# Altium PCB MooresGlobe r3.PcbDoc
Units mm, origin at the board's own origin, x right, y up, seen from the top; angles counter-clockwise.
Board outline 12 x 11 mm, 2 copper layers (Top Layer, Bottom Layer), stack 0.801 mm thick; 11 components, 6 nets, 24 pads, 3 vias.
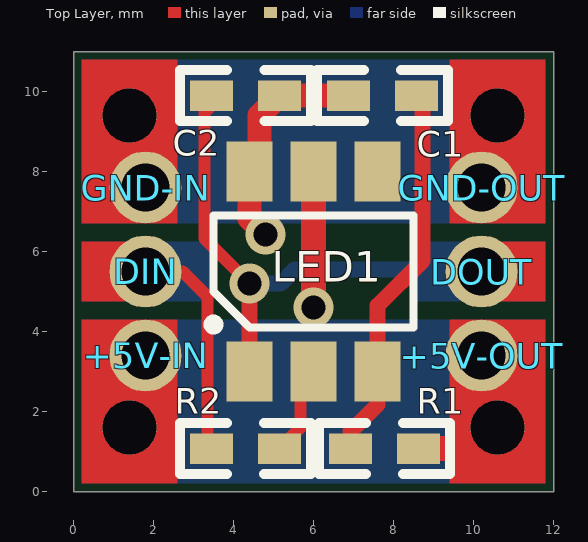
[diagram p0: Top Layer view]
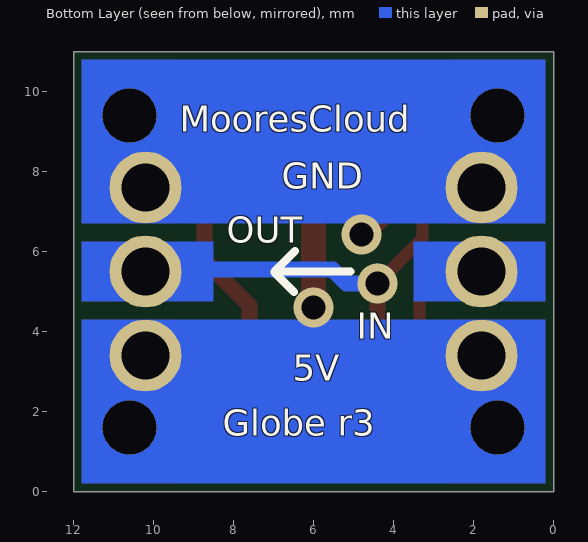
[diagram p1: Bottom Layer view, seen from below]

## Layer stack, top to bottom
Top Layer: signal copper 0.0356
Dielectric: core 0.73, FR-4, Dk 4.8
Bottom Layer: signal copper 0.0356

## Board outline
0,0 12,0 12,11 0,11

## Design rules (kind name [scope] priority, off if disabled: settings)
Clearance [All] p1: gap=0.254
HoleSize [All] p1: absolutevalues=TRUE maxlimit=3 minlimit=0.3 maxpercent=80.000 minpercent=20.000
MinimumSolderMaskSliver [All] p1: minsoldermaskwidth=0.152
PlaneClearance [All] p1: clearance=0.254
PolygonConnect [All] p1: connectstyle=Direct reliefconductorwidth=1.5 reliefentries=4 polygonreliefangle="90 Angle" airgapwidth=0.254
RoutingVias [All] p1: holewidth=0.4 width=0.6 viastyle="Through Hole" minholewidth=0.3 minwidth=0.6 maxholewidth=1 maxwidth=1.27
SilkToSilkClearance [All] p1 off: silktosilkclearance=0
SilkToSolderMaskClearance [IsPad] p1: minsilkscreentomaskgap=0.102 clearancetoexposedcopper=TRUE
SolderMaskExpansion [All] p1: expansion=0.102
Width [All] p1: maxlimit=1.27 minlimit=0.254 preferedwidth=0.254 minimp=50.000000 maximp=50.000000 favimp=50.000000
23 further rules are at their usual default settings.

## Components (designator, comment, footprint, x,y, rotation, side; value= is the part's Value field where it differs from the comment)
+5V-IN "+5V" "Solder Pad"#1 -2.3,1.7 r90 top
+5V-OUT "+5V" "Solder Pad"#2 14.027,2.326 r90 top
C1 "100n" ARA_0603 8.575,9.9 r180 top
C2 "470p" ARA_0603 3.45,9.9 r0 top
DIN "DIN" "Solder Pad"#3 -1.95,5.525 r90 top
DOUT "DOUT" "Solder Pad"#4 10.2,5.475 r90 top
GND-IN "GND" "Solder Pad"#5 -1.85,9.2 r90 top
GND-OUT "GND" "Solder Pad"#6 10.2,8.925 r90 top
LED1 "WS2812" PLCC6-IPC 6,5.5 r90 top locked
R1 "100R" ARA_0603 8.625,1.075 r180 top
R2 "0R" ARA_0603 5.15,1.075 r180 top

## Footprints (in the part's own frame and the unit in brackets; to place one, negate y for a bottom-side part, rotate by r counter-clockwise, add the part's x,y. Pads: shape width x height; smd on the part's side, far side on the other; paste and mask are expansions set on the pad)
ARA_0603 [mil]
  rect 42x30 smd: 1(0,0) 2(66.91,0)
  silkscreen extent -31,-25 98,25, body extent 0,-16 67,16, height 20
PLCC6-IPC [mm] "Leaded Chip Carrier, 12-Leads, Body 9.90x5.40mm, Pitch 1.600mm, IPC Medium Density"
  rect 1.5x1.15 smd: 1(-2.5,1.6) 2(-2.5,0) 3(-2.5,-1.6) 4(2.5,-1.6) 5(2.5,0) 6(2.5,1.6)
  silkscreen extent -1.45,-2.5 1.4,2.62, body extent -2.5,-2.5 2.5,2.5, height 1.61
"Solder Pad"#1 [mm]
  round 1.8 hole 1.2: 1(1.7,-4.1)
"Solder Pad"#2 [mm]
  round 1.8 hole 1.2: 1(1.074,3.827)
"Solder Pad"#3 [mm]
  round 1.8 hole 1.2: 1(-0.025,-3.75)
"Solder Pad"#4 [mm]
  round 1.8 hole 1.2: 1(0.025,0)
"Solder Pad"#5 [mm]
  round 1.8 hole 1.2: 1(-1.6,-3.65)
"Solder Pad"#6 [mm]
  round 1.8 hole 1.2: 1(-1.325,0)

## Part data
+5V-IN +5V-OUT DIN DOUT GND-IN GND-OUT: library part "Solder Pad", "Solder pad"
C1: library part CAP, "Capacitor Ceramic 100n 50V Y5V 0603"
C2: library part CAP, "Capacitor Ceramic 470p 50V NPO 0603"
LED1: "WorldSemi WS2812 Smart RGB LED"
R1 R2: library part "Res Semi", "Resistor 100R 0.1W 5% 0603"

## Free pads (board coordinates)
  round 1.35 hole 1.35 unplated mask+0: 0(1.4,1.6) 0(1.4,9.4) 0(10.6,1.6) 0(10.6,9.4)

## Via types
v1: diameter 1, hole 0.6, Top Layer to Bottom Layer, tented both sides, 3 vias

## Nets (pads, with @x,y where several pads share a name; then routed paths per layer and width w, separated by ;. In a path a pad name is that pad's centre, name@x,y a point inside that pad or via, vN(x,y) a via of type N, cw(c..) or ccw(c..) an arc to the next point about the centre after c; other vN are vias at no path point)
5V: +5V-IN.1 +5V-OUT.1 LED1.5 pad.0@1.4,1.6 pad.0@10.6,1.6 R1.1 | length 10.2
  Top Layer w0.635: v1(6,4.6) LED1.5 ; R1.1 9.7,1.075 ; +5V-OUT.1@9.85,3.05 +5V-OUT.1
  Bottom Layer w0.635: +5V-IN.1 5.725,3.4 6,3.675 v1(6,4.6)
DIN: DIN.1 R2.2 | length 5.8
  Top Layer w0.3: DIN.1 2.725,5.5 3.35,4.875 3.35,1.175 3.375,1.15 R2.2@3.6,1.15
DOUT: C2.1 DOUT.1 LED1.1 | length 13.7
  Top Layer w0.3: C2.1 3.45,9.65 3.275,9.475 3.275,6.325 v1(4.4,5.2)
  Top Layer w0.4: LED1.1 v1(4.4,5.2)
  Bottom Layer w0.4: v1@4.4,5.5 v1(4.4,5.2) 5.175,5.2 5.529,5.554 10.146,5.554 DOUT.1
GND: C1.2 C2.2 GND-IN.1 GND-OUT.1 LED1.6 pad.0@1.4,9.4 pad.0@10.6,9.4 | length 5.7
  Top Layer w0.6: v1(4.8,6.425) 4.4,6.825 LED1.6 4.65,8.25 4.65,9.4 C2.2 6,9.9 ; 6.025,9.9 C1.2
NetC1_1: C1.1 LED1.3 R1.2 | length 9.6
  Top Layer w0.4: R1.2 6.925,1.5 7.6,2.175 LED1.3 7.6,4.65 8.725,5.775 8.725,9.75 C1.1
NetLED1_2: LED1.2 R2.1 | length 1.8
  Top Layer w0.3: R2.1 5.675,1.6 LED1.2@5.675,2.675
pads on no net: LED1.4

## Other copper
Top Layer:
  rectangle net GND: 9.4,6.7 11.8,10.8
  rectangle net 5V: 9.4,0.2 11.8,4.3
  rectangle net 5V: 0.2,0.2 2.6,4.3
  rectangle net GND: 0.2,6.7 2.6,10.8
  rectangle net 5V: 9.75,3 11.8,4
  rectangle net GND: 9.75,7 11.8,8
  rectangle net GND: 0.2,7 2.25,8
  rectangle net 5V: 0.2,3 2.25,4
  rectangle net DIN: 0.2,4.75 2.25,6.25
  rectangle net DOUT: 9.75,4.75 11.8,6.25
Bottom Layer:
  rectangle net 5V: 0.2,0.2 11.8,4.3
  rectangle net GND: 0.2,6.7 11.8,10.8
  rectangle net 5V: 8.5,2.6 11.8,4.1
  rectangle net GND: 8.5,6.9 11.8,8.4
  rectangle net GND: 0.2,6.9 3.5,8.4
  rectangle net 5V: 0.2,2.6 3.5,4.1
  rectangle net DIN: 0.2,4.75 3.5,6.25
  rectangle net DOUT: 8.5,4.75 11.8,6.25

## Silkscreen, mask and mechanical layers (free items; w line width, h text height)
Bottom Overlay:
  lines w0.203: 5.075,5.5 6.975,5.5 6.463,6.013 ; 6.488,4.988 6.975,5.475
  text "MooresCloud" at 9.35,9 h0.65
  text "GND" at 6.8,7.575 h0.65
  text "OUT" at 8.175,6.225 h0.65
  text "IN" at 4.925,3.825 h0.65
  text "5V" at 6.525,2.775 h0.65
  text "Globe r3" at 8.275,1.4 h0.65
Mechanical 1:
  the board outline again, w0.6
Mechanical 2:
  text "Top Layer Component Keep Out Areas" at 21,4 h1
Mechanical 3:
  rectangle: 5.25,0 6.75,1.4
  rectangle: 5.25,9.6 6.75,11
  text "Bottom Layer Component Keep Out Areas" at 21,2 h1
Drill Drawing:
  lines w0.1: 21,-3.25 79.25,-3.25 ; 21,-1.25 79.25,-1.25 ; 21,7.5 79.25,7.5 ; 21,9.5 79.25,9.5 ; 21,11.5 79.25,11.5 ; 21,13.5 79.25,13.5 ; 21,15.5 79.25,15.5 ; 21,17.5 79.25,17.5 ; 21,19.5 79.25,19.5 ; 21,21.5 79.25,21.5 ; 33.5,-5.25 33.5,1 ; 33.5,5.5 33.5,23.5 ; 0,0 0,11 12,11 12,0 0,0 ; 21,-5.25 21,1 79.25,1 79.25,-5.25 21,-5.25 ; 21,5.5 79.25,5.5 79.25,23.5 21,23.5 21,5.5
  text ".legend" at 22.25,28.75 h1
  text "BOARD SIZE:" at 21.5,22 h1
  text "12.00mm x 11.00mm" at 34.5,22 h1
  text "LAYERS:" at 21.5,20 h1
  text "2" at 34.5,20 h1
  text "MATERIAL:" at 21.5,18 h1
  text "FR4 0.8mm" at 34.5,18 h1
  text "COPPER:" at 21.5,16 h1
  text "35um (after plating)" at 34.5,16 h1
  text "PTH PLATING:" at 21.5,14 h1
  text "20um (minimum)" at 34.5,14 h1
  text "FINISH:" at 21.5,12 h1
  text "ROHS HAL" at 34.5,12 h1
  text "OVERLAY:" at 21.5,10 h1
  text "Black, 2 sides" at 34.5,10 h1
  text "SOLDER MASK:" at 21.5,8 h1
  text "White, 2 sides" at 34.5,8 h1
  text "PROFILING:" at 21.5,6 h1
  text "V-Groove" at 34.5,6 h1
  text "FILE NAME:" at 21.5,-0.75 h1
  text ".Pcb_File_Name_No_Path" at 34.5,-0.75 h1
  text "LAYER:" at 21.5,-2.75 h1
  text ".Plot_File_Name" at 34.5,-2.75 h1
  text "PRINT DATE:" at 21.5,-4.75 h1
  text ".Print_Date" at 34.5,-4.75 h1
Mechanical 20:
  the board outline again, w0.1

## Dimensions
0,0 to 0,11 on Drill Drawing
0,0 to 12,0 on Drill Drawing
0,-1 to 12,-1 on Mechanical 16
-1,0 to -1,11 on Mechanical 16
